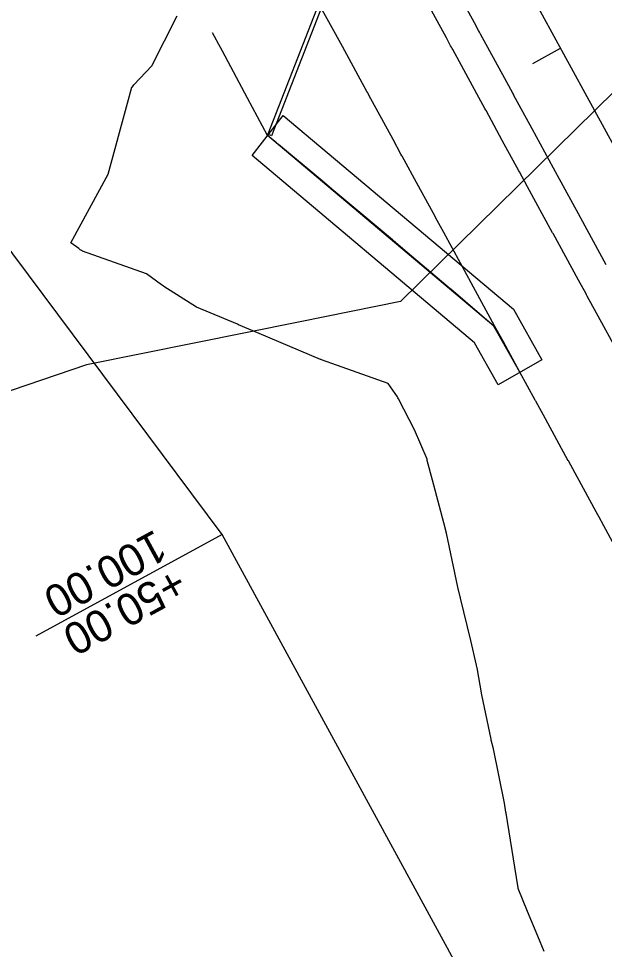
# Model space of a CAD drawing. Extents: x 1627557 to 1636561, y 783843 to 794002.
# Drawn here: x 1627975.8 to 1628086.3, y 784710.3 to 784885.9 of the extents above; entities that cross this region are included whole.
import ezdxf

# ---------------------------------------------------------------- set-up
doc = ezdxf.new("R2010")
doc.units = 0
for name, color, linetype in [('25 FT Buffer', 7, 'Continuous'), ('Ditch Lines', 7, 'Continuous'), ('Ditch with Dumped RipRap', 7, 'Continuous'), ('R_Clearzone', 7, 'Continuous'), ('R_Culvert', 7, 'Continuous'), ('R_Ditch', 7, 'Continuous'), ('R_Horz Alg', 7, 'Continuous'), ('R_Horz Alg Annot', 7, 'Continuous'), ('R_Proposed Const Limits', 7, 'Continuous'), ('R_Proposed Road', 7, 'Continuous'), ('R_Proposed Shoulder', 7, 'Continuous'), ('R_ROW', 7, 'Continuous'), ('R_ROW Annot', 7, 'Continuous')]:
    doc.layers.add(name, color=color, linetype=linetype)

msp = doc.modelspace()

# ---------------------------------------------------------------- linework, layer by layer
at = {"layer": '25 FT Buffer'}
msp.add_lwpolyline([(1628128.73, 784912.02), (1628047.84, 784832.47), (1628028.94, 784828.64), (1627988.66, 784820.54), (1627954.84, 784809.03), (1627927.06, 784808.64), (1627894.29, 784799.05), (1627847.27, 784784.48), (1627792.52, 784755.67), (1627716.91, 784734.64)], dxfattribs=at)
at = {"layer": 'Ditch Lines'}
msp.add_line((1628070.41, 784819.15), (1628066.15, 784826.79), dxfattribs=at)
msp.add_lwpolyline([(1628070.41, 784819.15), (1628065.49, 784827.87), (1628022.8, 784863.82)], dxfattribs=at)
at = {"layer": 'Ditch with Dumped RipRap'}
msp.add_lwpolyline([(1628066.28, 784816.79), (1628061.83, 784824.68), (1628019.86, 784860.03), (1628025.75, 784867.6), (1628069.16, 784831.05), (1628074.53, 784821.52)], close=True, dxfattribs=at)
at = {"layer": 'R_Clearzone'}
msp.add_lwpolyline([(1628089.56, 784784.04), (1628085.76, 784791), (1628085.73, 784791.05), (1628085.63, 784791.23), (1628084.77, 784792.82), (1628079.98, 784801.6), (1628079.54, 784802.41), (1628079.53, 784802.43), (1628079.51, 784802.45), (1628075.19, 784810.37), (1628073.4, 784813.68), (1628073.35, 784813.77), (1628073.29, 784813.87), (1628070.41, 784819.15), (1628067.28, 784824.9), (1628067.15, 784825.13), (1628067.06, 784825.3), (1628065.62, 784827.93), (1628060.84, 784836.7), (1628060.83, 784836.71), (1628060.82, 784836.74), (1628060.77, 784836.83), (1628056.05, 784845.49), (1628054.48, 784848.36), (1628054.48, 784848.36), (1628054.4, 784848.51), (1628051.26, 784854.27), (1628048.2, 784859.89), (1628048.15, 784859.98), (1628047.96, 784860.32), (1628046.47, 784863.05), (1628041.91, 784871.42), (1628041.81, 784871.6), (1628041.69, 784871.83), (1628041.53, 784872.12), (1628040.73, 784873.59), (1628036.9, 784880.61), (1628032.11, 784889.39)], dxfattribs=at)
at = {"layer": 'R_Culvert'}
for p, q in [((1628032.48, 784888.71), (1628022.82, 784864.04)), ((1628032.99, 784887.94), (1628023.51, 784863.76)), ((1628023.51, 784863.76), (1628022.82, 784864.04))]:
    msp.add_line(p, q, dxfattribs=at)
at = {"layer": 'R_Ditch'}
msp.add_lwpolyline([(1628089.56, 784784.04), (1628085.76, 784791), (1628085.73, 784791.05), (1628085.63, 784791.23), (1628084.77, 784792.82), (1628079.98, 784801.6), (1628079.54, 784802.41), (1628079.53, 784802.43), (1628079.51, 784802.45), (1628075.19, 784810.37), (1628073.4, 784813.68), (1628073.35, 784813.77), (1628073.29, 784813.87), (1628070.41, 784819.15), (1628067.28, 784824.9), (1628067.15, 784825.13), (1628067.06, 784825.3), (1628065.49, 784827.87), (1628057.34, 784834.8), (1628057.33, 784834.81), (1628057.3, 784834.83), (1628057.23, 784834.9), (1628049.15, 784841.73), (1628046.47, 784843.99), (1628046.47, 784843.99), (1628046.33, 784844.11), (1628040.94, 784848.65), (1628035.68, 784853.06), (1628035.59, 784853.13), (1628035.28, 784853.4), (1628032.71, 784855.55), (1628024.85, 784862.12), (1628024.68, 784862.25), (1628024.46, 784862.44), (1628024.18, 784862.67), (1628022.8, 784863.82), (1628019.04, 784870.87), (1628014.31, 784879.69), (1628013.25, 784881.66), (1628013.23, 784881.69), (1628013.16, 784881.82), (1628012.41, 784883.21)], dxfattribs=at)
at = {"layer": 'R_Horz Alg'}
msp.add_line((1628236.53, 784589.68), (1627810.31, 785371.39), dxfattribs=at)
at = {"layer": 'R_Horz Alg Annot'}
msp.add_lwpolyline([(1628072.81, 784877.41), (1628078.08, 784880.29)], dxfattribs=at)
at = {"layer": 'R_Proposed Const Limits'}
msp.add_lwpolyline([(1628074.97, 784709.89), (1628073.76, 784712.78), (1628071.84, 784717.43), (1628070.09, 784721.78), (1628070.05, 784721.95), (1628069.99, 784722.28), (1628069.17, 784727.36), (1628067.79, 784735.98), (1628067.78, 784735.99), (1628067.76, 784736.16), (1628067.49, 784737.84), (1628065.41, 784748.09), (1628065, 784749.73), (1628064.99, 784749.74), (1628064.95, 784749.92), (1628063.22, 784758.29), (1628062.31, 784763.38), (1628062.28, 784763.52), (1628062.21, 784763.91), (1628061.15, 784768.55), (1628059.17, 784776.5), (1628059.16, 784776.56), (1628059.11, 784776.77), (1628058.66, 784778.58), (1628056.53, 784788.81), (1628056.28, 784789.73), (1628056.28, 784789.75), (1628056.27, 784789.78), (1628053.9, 784798.77), (1628052.93, 784802.52), (1628052.9, 784802.62), (1628052.87, 784802.73), (1628050.51, 784808.3), (1628047.5, 784814.12), (1628047.38, 784814.35), (1628047.29, 784814.52), (1628045.56, 784817), (1628032.96, 784821.5), (1628032.94, 784821.51), (1628032.9, 784821.53), (1628032.79, 784821.57), (1628021.18, 784826.48), (1628017.33, 784828.1), (1628017.33, 784828.1), (1628017.13, 784828.19), (1628009.37, 784831.44), (1628003.2, 784835.35), (1628003.11, 784835.42), (1628002.76, 784835.67), (1627999.95, 784837.69), (1627987.9, 784841.97), (1627987.72, 784842.1), (1627987.47, 784842.27), (1627987.17, 784842.49), (1627985.66, 784843.57), (1627992.73, 784856.53), (1627996.36, 784869.9), (1627997.18, 784872.9), (1627997.29, 784872.99), (1627997.6, 784873.34), (1628000.97, 784876.97), (1628005.74, 784886.41)], dxfattribs=at)
at = {"layer": 'R_Proposed Road'}
msp.add_lwpolyline([(1628086.69, 784839.42), (1628081.91, 784848.19), (1628081.9, 784848.2), (1628081.89, 784848.23), (1628081.84, 784848.32), (1628077.12, 784856.98), (1628075.56, 784859.85), (1628075.55, 784859.85), (1628075.47, 784860), (1628072.33, 784865.76), (1628069.27, 784871.38), (1628069.22, 784871.47), (1628069.04, 784871.81), (1628067.54, 784874.54), (1628062.98, 784882.91), (1628062.89, 784883.08), (1628062.76, 784883.32), (1628062.6, 784883.61), (1628061.8, 784885.08), (1628057.97, 784892.1)], dxfattribs=at)
at = {"layer": 'R_Proposed Shoulder'}
msp.add_lwpolyline([(1628089.1, 784822.48), (1628086.21, 784827.77), (1628083.08, 784833.51), (1628082.95, 784833.74), (1628082.86, 784833.92), (1628081.42, 784836.55), (1628076.64, 784845.32), (1628076.64, 784845.33), (1628076.62, 784845.36), (1628076.57, 784845.45), (1628071.85, 784854.11), (1628070.29, 784856.98), (1628070.29, 784856.98), (1628070.21, 784857.13), (1628067.06, 784862.89), (1628064, 784868.51), (1628063.95, 784868.59), (1628063.77, 784868.93), (1628062.28, 784871.67), (1628057.71, 784880.04), (1628057.62, 784880.21), (1628057.49, 784880.45), (1628057.33, 784880.74), (1628056.53, 784882.21), (1628052.7, 784889.23)], dxfattribs=at)
at = {"layer": 'R_ROW'}
for p, q in [((1628014.22, 784788.52), (1627971.93, 784845.19)), ((1628133.89, 784569.02), (1628014.22, 784788.52))]:
    msp.add_line(p, q, dxfattribs=at)
at = {"layer": 'R_ROW Annot'}
msp.add_lwpolyline([(1628014.22, 784788.52), (1627979.1, 784769.37)], dxfattribs=at)

# ---------------------------------------------------------------- texts
for s, p in [('100.00', (1628001.57, 784789.59)), ('+50.00', (1628005.4, 784782.57))]:
    msp.add_text(s, height=6, rotation=208.601, dxfattribs=at).set_placement(p)

doc.saveas('drawing.dxf')
